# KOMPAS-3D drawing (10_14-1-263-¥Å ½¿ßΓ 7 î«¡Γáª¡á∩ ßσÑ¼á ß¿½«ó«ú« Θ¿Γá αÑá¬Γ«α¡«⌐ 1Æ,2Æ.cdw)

Views: Вид 1
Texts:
  Сергей
  Текст на чертеже
  Размерные надписи
  Шероховатость
  Линия-выноска #1
  Линия-выноска #2
  Линия-выноска #3
  Отклонения формы и база
  Заголовок таблицы
  Ячейка таблицы
  Стрелка вида
  Обозначение изменения
  Фигурная скобка
  Номер узла
  Марка координационной оси
  VRCB
  Выносная надпись
  Обозначение узла
  Марка/позиционное обозначение с линией-выноской
  Марка/позиционное обозначение на линии
  Марка/позиционное обозначение без линии-выноски
  Normal
  Body Text
  heading 1
  Знак Знак Знак Знак Знак Знак
  Verdana
  Лит-Масса-Масштаб
  Материал-Предприятие
  Simplex
  Txt
  цепи
  Подпись в квадратике
  ссылки
  табл
  Без имени
  Маркировка
  клеммы, контакты
  тексты табл
  Тексты. 3,2
  ЗОНА_привяз
  Additional DXF text style 0
  Обычный
  Термин
  Список определений
  Адрес
  Цитаты
  Форматированный
  Courier New
  Z-конец формы
  Z-начало формы
  текст переноса
  txt
  MS Sans Serif
  Title Specification
  Body Specification ( left align )
  Body Specificaton ( centered )
  Текст 3,5
  ООббыыччнныыйй
  Definition Term
  Definition List
  Address
  Blockquote
  Preformatted
  z-Bottom of Form
  z-Top of Form
  heading 8
  heading 3
  heading 6
  heading 7
  ТекстШаг1
  russ
  ТТееррммиинн
  ССппииссоокк ооппррееддееллеенниийй
  ААддрреесс
  ЦЦииттааттыы
  ФФооррммааттиирроовваанннныыйй
  Z-ккооннеецц ффооррммыы
  Z-ннааччааллоо ффооррммыы
  Абзац Знак
  heading 2
  heading 4
  heading 5
  heading 9
  Body Text 3
  Title
  rustxt
  AGOpus
  footer
  Table Contents
  Table Heading
  Tahoma
  маркировка
  Денис
  GOST 2.304 type A
  TXT
  ГОСТ_МНЕ
  ESK - Обозначение
  FR5
  NormalParagraphStyle
  header
  ISOCP
  ISOCTEUR
  Шрифт 2.5
  Заголовки
  style2
  HeliosLight
  Pa3
  Pa1
  Три с половиной
  RUSTXT
  CNBNDG+TimesNewRoman
  Subtitle
  CC С?т?и?л?ь? П?о? ц?е?н?т?р?у?
  eskd1
  Pa15
  Pa18
  romanc
  Аппараты
  Ссылки
  подписи
  Состав чартежа
  Клеммник текст
  ячейка табл.
  Пояснения
  SignaColumn-Light
  ISOCPEUR
  Основной текст
  Блок
  XT2
  Acti 9 iC60N 2P
  QF1
  QS1.2
  QS1.6
  QF1.1
  QF2.1
  QF2
  QF6
  XT3
  XT4
  QS1.4
  QF6.1
  QS1.8
  QF1.3
  QF2.3
  QF6.3
  XT2.2
  XT2.9
  XT2.5
  XT2.10
  XT2.7
  XT2.11
  Acti 9 iC60N 3P
  QF3
  Acti 9 iSW 4P
  QS1
  XT1
  XT2.1
  XT2.4
  XT2.6
  XT2.8
  QF3.1
  QF4.1
  QF5.1
  QF3.3
  QF4.3
  QF3.5
  QF4.5
  KM1.7
  KM2.7
  QF5.3
  Acti 9 iCT 4P
  KM1
  QF4
  KM2
  XT2.13
  Поз.
  обознач.
  Перечень элементов
  Кол.
  XT3, XT4
  XT5
  XT6, XT7
  XT8, XT9
  QF1, QF2,
  QF5, QF6
  КМ1
  КМ2
  RK1-RK5
  - проходная клемма на 2 проводника (желто-зеленая), шт.
  - гребешковая перемычка 2-канальная, шт.
  Клеммная сборка, WAGO, в составе, шт.:
  - проходная клемма на 2 проводника (оранжевая), шт.
  - проходная клемма на 2 проводника (синяя), шт.
  - гребешковая перемычка 2-канальная, шт
  Выключатель нагрузки Acti9 iSW 4P 63A, шт.
  Автоматический выключатель Acti 9 iC60N 2P 6A, хар-ка В, шт.
  Автоматический выключатель Acti 9 iC60N 3P 6A, хар-ка C, шт.
  Автоматический выключатель Acti 9 iC60N 3P 20A, хар-ка B, шт.
  Контакторы с ручным управлением Acti 9 iCT 4P 25А, Uупр=220В
  Контакторы с ручным управлением Acti 9 iCT 4P 63А, Uупр=220В
  Мультифункциональный цифровой термостат Elko ep TER-9, шт.
  Температурный сенсор Elko ep TZ-12, шт.
  Клеммная коробка
  Арт. 2006-1207
  Арт. 2006-402
  Арт. 2002-1202
  Арт. 2002-1204
  Арт. 2002-402
  Арт. A9S60463
  Арт. A9F78206
  Арт. A9F79306
  Арт. A9F78120
  Арт. A9C21834
  Арт. A9C20162
  ОПУ, КК1
  Арт. 2006-1204
  Арт. 2006-1202
  Вывод 1
  Вывод 2
  ELCO ep TER-9
  XT8
  XT5.6
  XT9
  XT5.4
  XT5.7
  QF5
  XT2.3
  XT5.1
  XT5.2
  XT8.1
  XT8.2
  XT5.3
  XT9.2
  XT5.5
  XT9.1
  в схему
  обогрева
  (см. лист 8  )
  XT2.12
  XT6
  XT7
  Вентилятор В2
  (см. лист 5,6)
  XT2.14
  Шкаф A1,A2
  Освещение
  Розетка
  Вентилятор В1
  Реакторная 1Т,2Т
  ПС 110 кВ Опорная
  TZ-12
  RK1
  RK3
  RK2
  QF5.4
  QF5.2
  Примечания:
  шкафа выполнить проводом ПВ-1х2,5;
  термостата A1 установлена дифференция 15   C, для термостата A2 установлена дифференция 20
  установлена температура срабатывания +30  C с дифференцией +10   C и гистерезис 2  C.
  RK5
  RK4
  в ЩСН
  (см. 10/14-1-020-ЭП)
  CONTINUOUS0
  K5LT_THIN_RGB_0_0_0_THICK_0.18
  ACAD_ISO02W100_RGB_0_0_0_SC_1_THICK_0.13
  POLYLINE_STYLE_0.18_RGB_0_0_0
  POLYLINE_STYLE_0.25_RGB_0_0_0
  POLYLINE_STYLE_0.60_RGB_0_0_0
  GOST2.303 6_RGB_0_0_0_SC_0.1_THICK_0.13
  CHAIN_RGB_0_0_0_SC_1_THICK_0.13
  POLYLINE_STYLE_0.30_RGB_0_0_0
  СONTINUOUS_RGB_0_0_0_THICK_0.13
  ByLayer_RGB_0_0_0_THICK_0.13
  K5LT_BASIC_RGB_0_0_0_THICK_0.18
  Стили документа
  Реактор
  Разраб.
  Ромин
  Калинин
  Общие технические условия на средний ремонт
  Реконструкция ПС 110 кВ Опорная
  (замена трансформаторов 16МВА на 40МВА)
  Гаврилов
  Монтажная схема силового щита
  реакторной 1Т,2Т
  Отдел ПС
Dimensions and other numbers on the sheet: 10/14-1-263-ЭП; 7; 3,2 (надписи); 2,5 (контакты, клеммы); 3.2 (текст); 3,2_; 2,5; 3,2 элементы; 3,2 линия; 3,2 таблица; 3,2; 5; 2,5_01; 2,5_3; 3,5_01; 3,5_tabl; 5_заголовок; 2,3_; 3,2_зона не привяз; 3,5; 3.5; 1,8; 2.5 курсив; 2.5; 3.2 маркировка; 2,5 грязносинь; 3,2 (Зоны); 2.5_Э5_надписи; 2.5_Э5_ссылки; 2.5_кабель; 3.2; 2.5 надписи; 3.2 фиол; 5,0_белый_подчёркнутый; 3 и 5; 3; 2; 1; 4; 6; 8; 9; 10; 11; 12; 13; 14; 15; 16; 18; 25; 28; 26; 11.12; 04-2012-2-060-АОВ-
